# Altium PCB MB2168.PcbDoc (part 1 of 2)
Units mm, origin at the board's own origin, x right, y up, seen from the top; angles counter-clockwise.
Board outline 43 x 47 mm, 2 copper layers (Top Layer, Bottom Layer), stack 0.996 mm thick; 88 components, 71 nets, 358 pads, 587 vias.
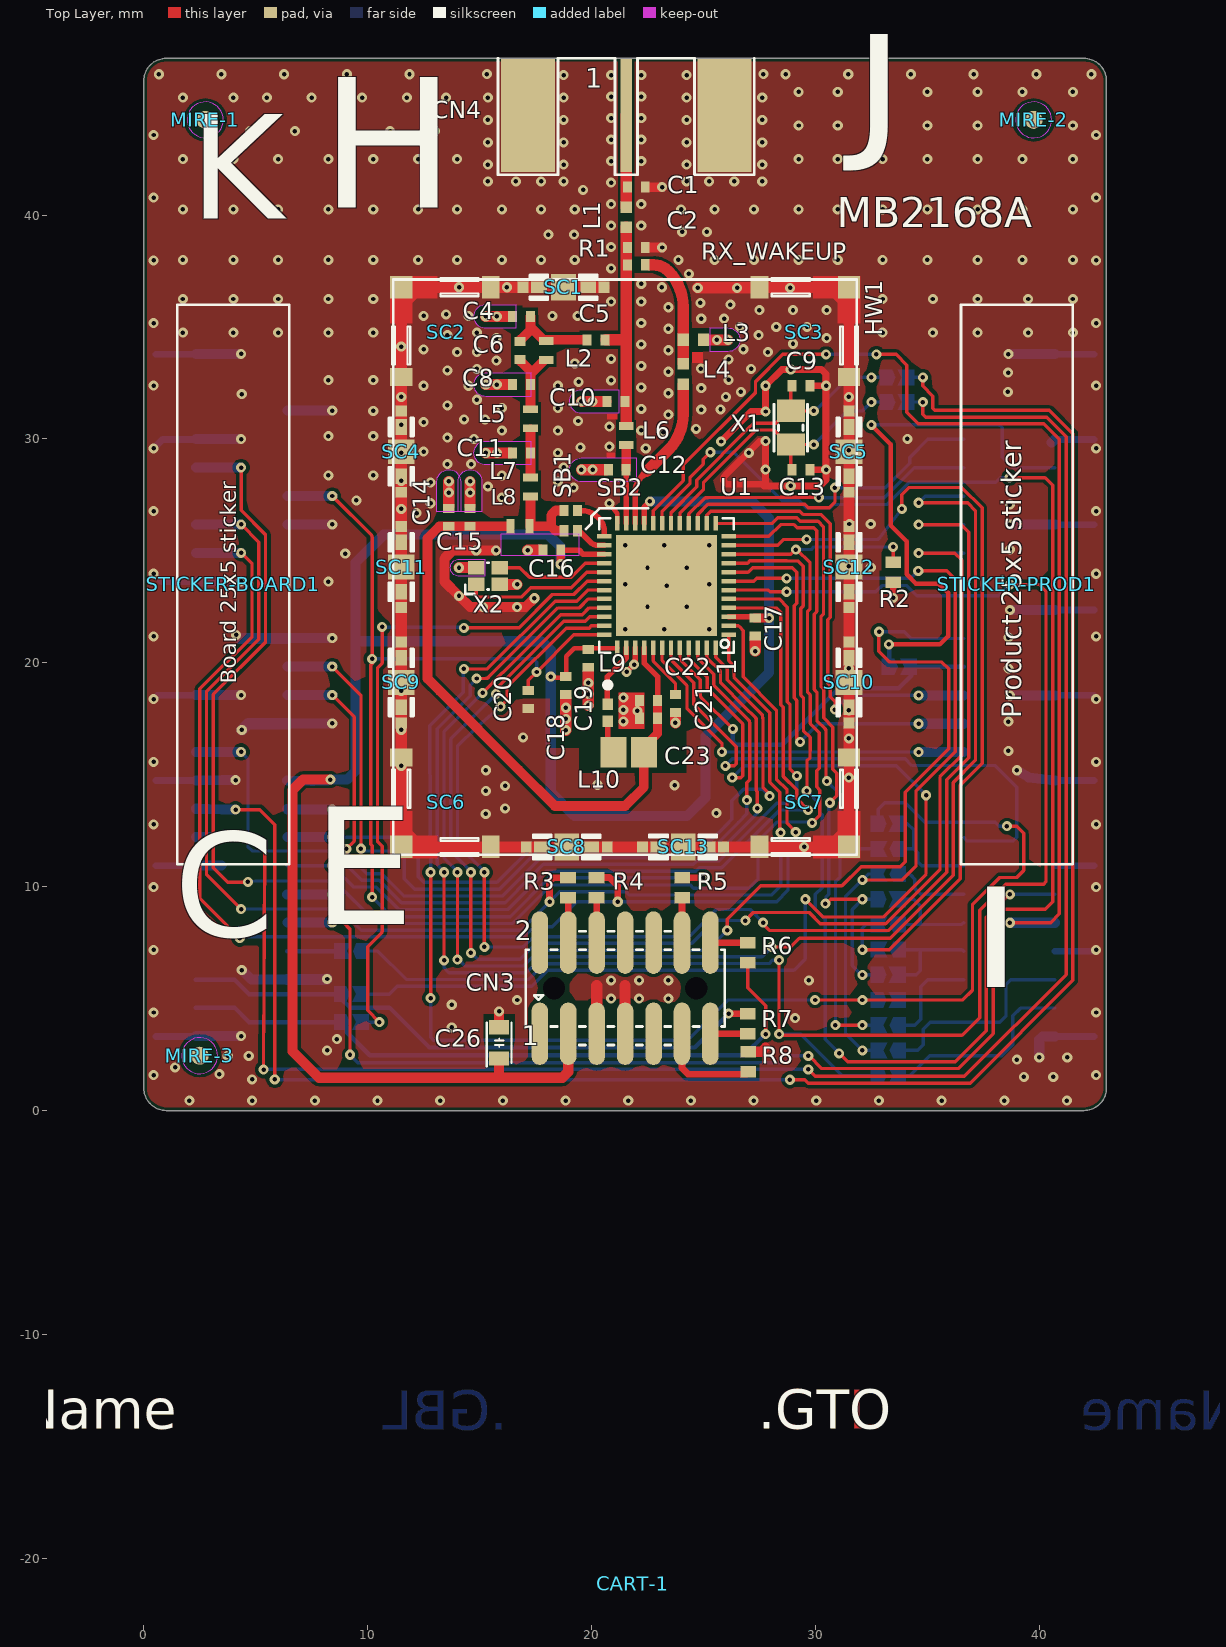
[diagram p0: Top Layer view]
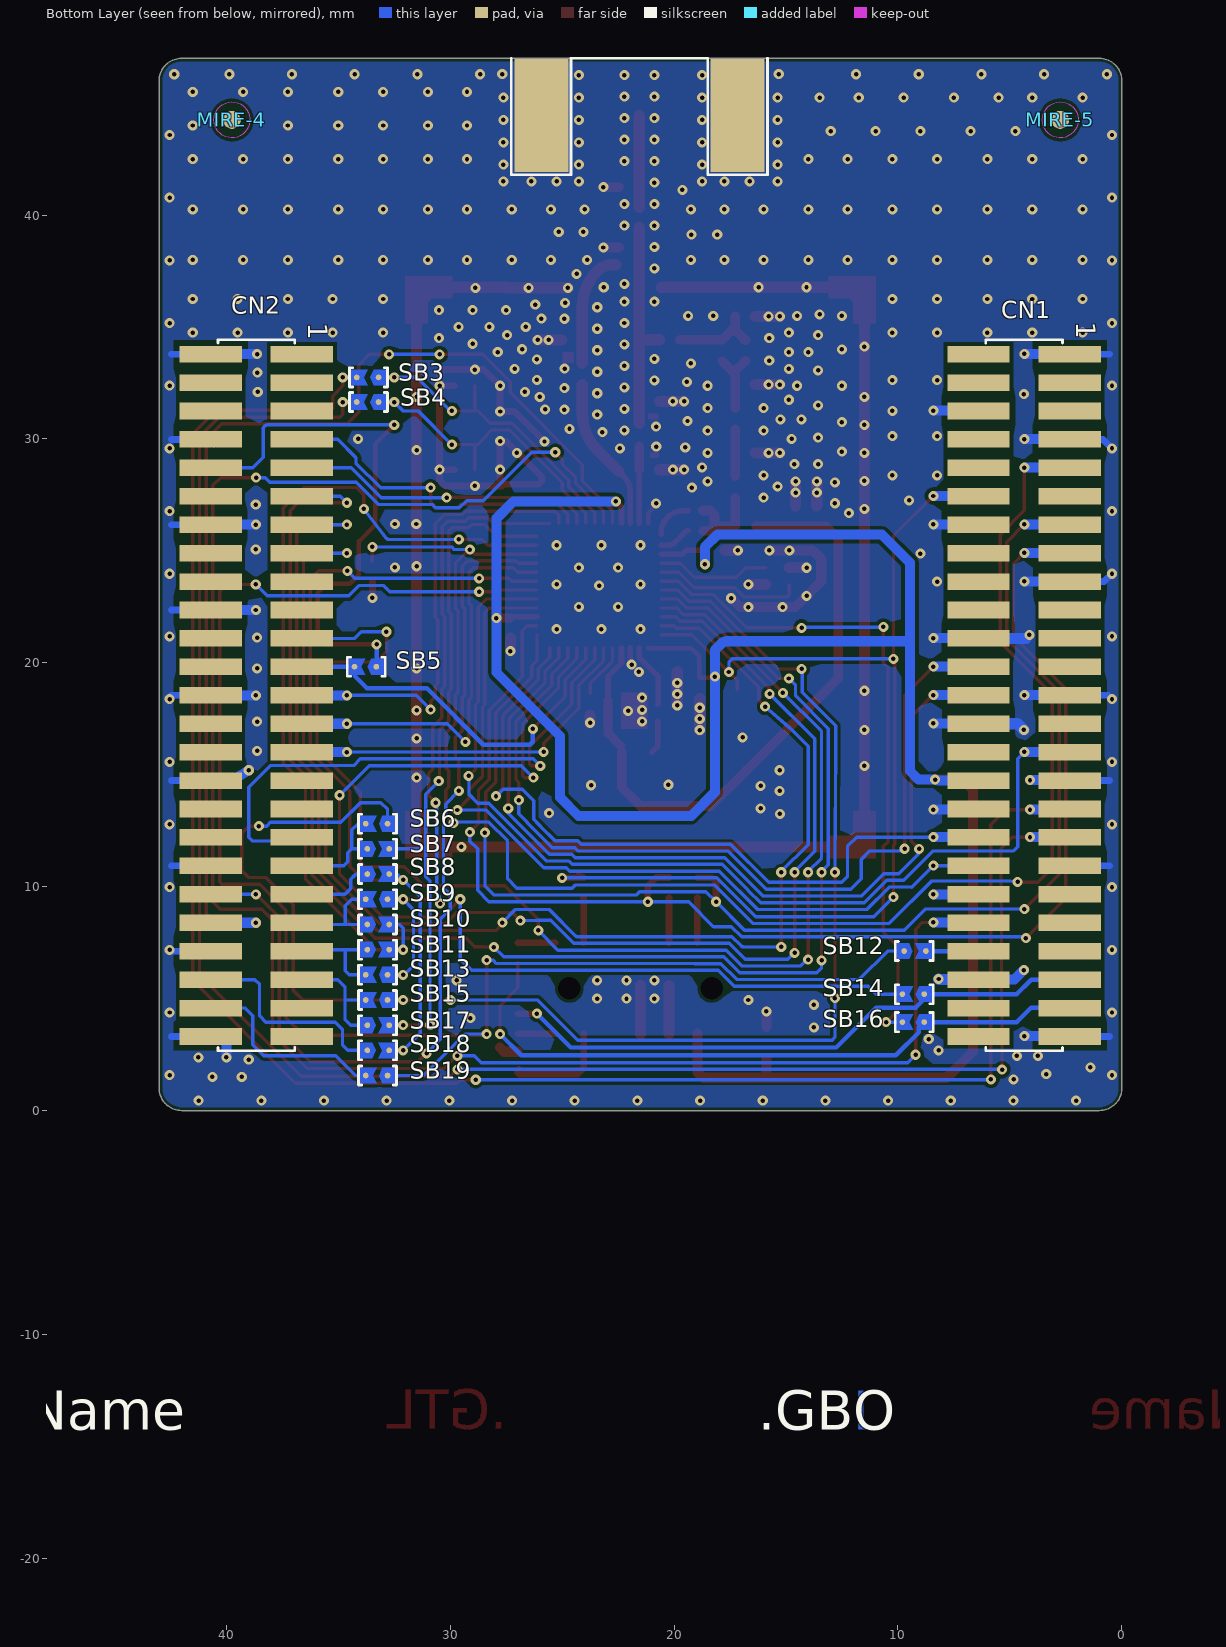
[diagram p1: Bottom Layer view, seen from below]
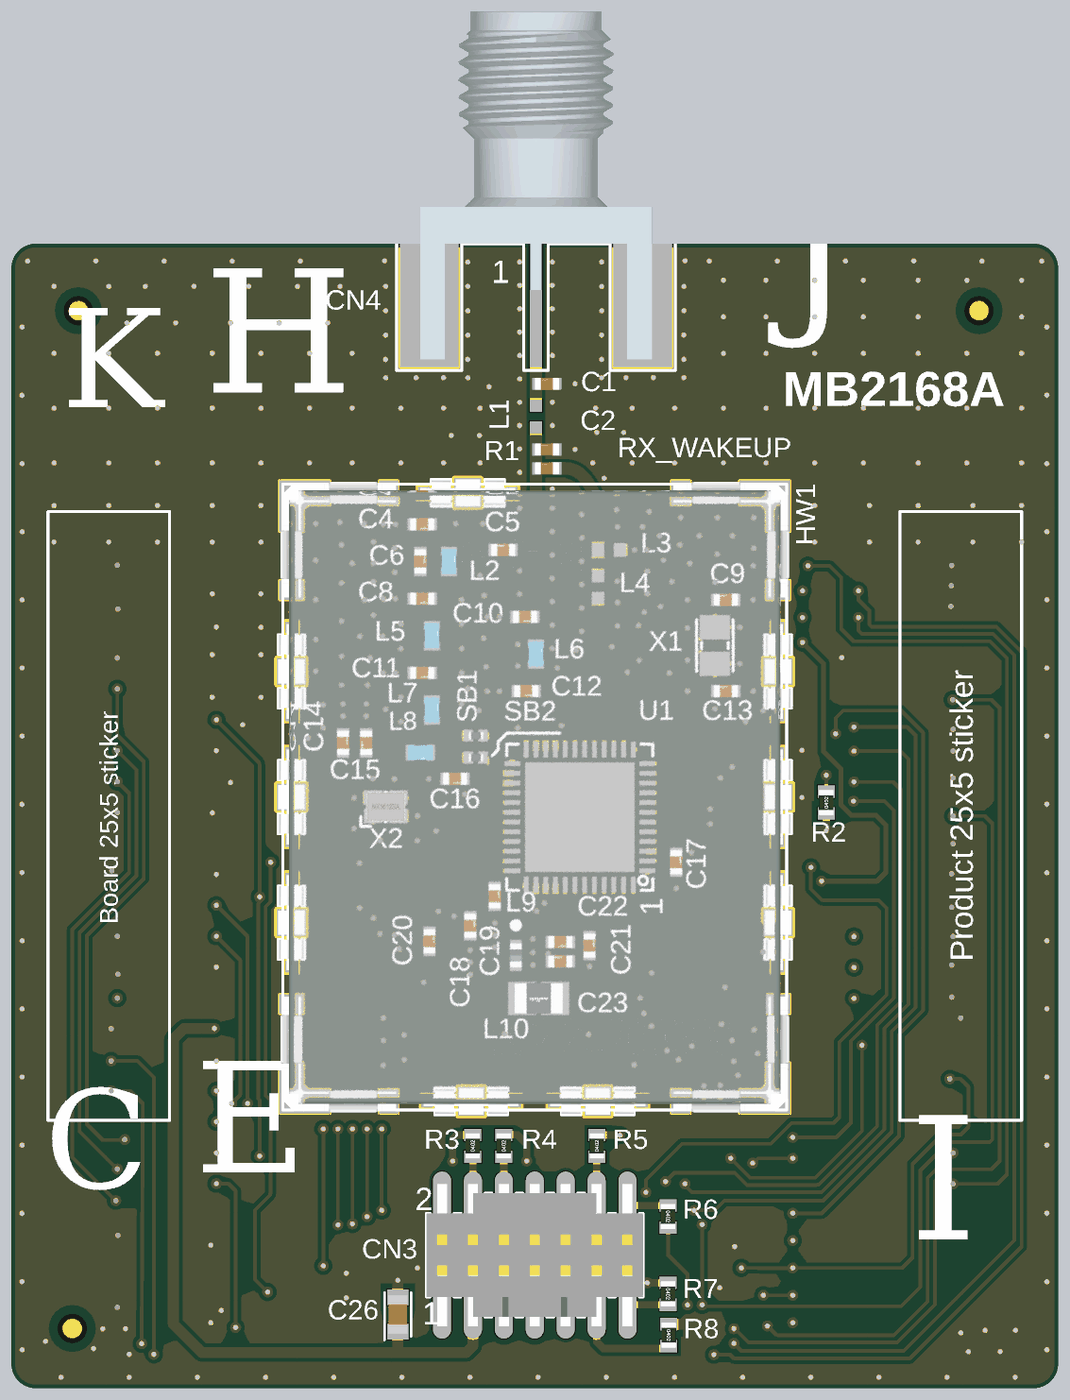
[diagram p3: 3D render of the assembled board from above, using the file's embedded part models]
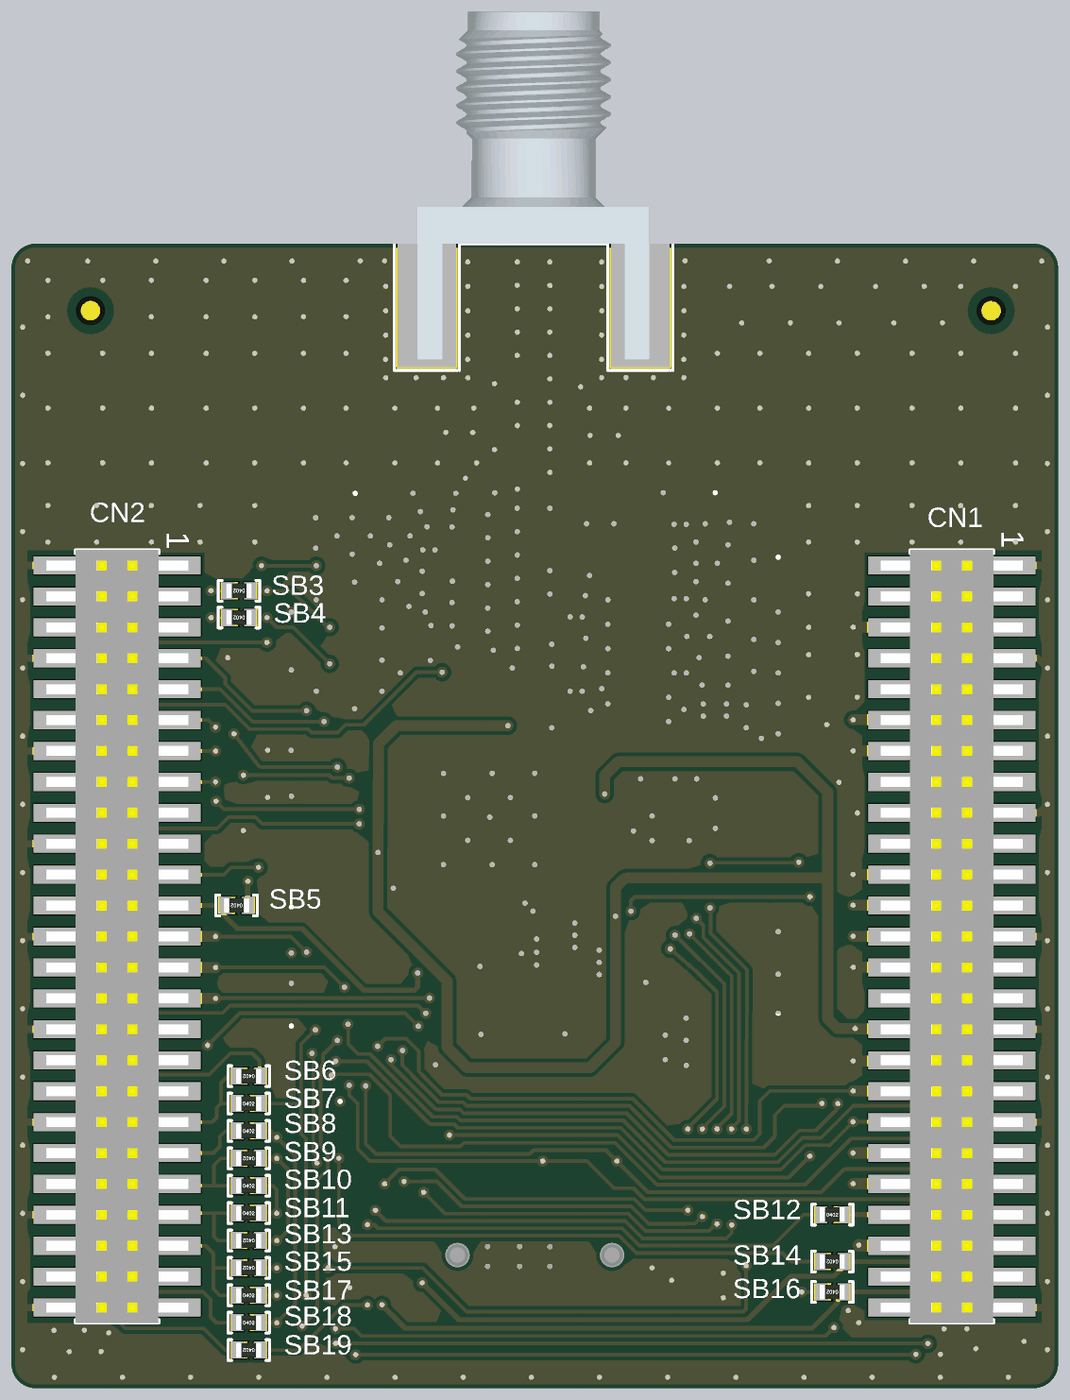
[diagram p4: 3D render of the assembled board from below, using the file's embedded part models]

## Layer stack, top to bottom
Top Solder: solder mask 0.0102, Solder Resist, Dk 3.5
Top Layer: signal copper 0.0406
Dielectric 2: core 0.9144, FR4, Dk 4.3
Bottom Layer: signal copper 0.0406
Bottom Solder: solder mask 0.0102, Solder Resist, Dk 3.5

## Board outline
0,1 ccw(c1,1) 1,0 42,0 ccw(c42,1) 43,1 43,46 ccw(c42,46) 42,47 1,47 ccw(c1,46) 0,46

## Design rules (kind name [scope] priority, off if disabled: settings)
BoardOutlineClearance [All] p1: gap=0.14 ignorepadtopadclearanceinfootprint=FALSE
Clearance Clearance_Keepout [All vs IsKeepOut] p1: gap=0.15 ignorepadtopadclearanceinfootprint=TRUE except(0: Poly-Region)
Clearance Clearance_RF-50R [InNetClass('NC_RF-50R')] p2: gap=0.018 ignorepadtopadclearanceinfootprint=FALSE
Clearance Clearance_Default_Same-net_GND [InNet('GND')] p3: gap=0.15 ignorepadtopadclearanceinfootprint=TRUE except(0: Arc-SMDPad Arc-THPad Arc-Via Track-SMDPad Track-THPad Track-Via SMDPad-Via SMDPad-Hole Via-Via Via-Fill Fill-Region; 0.1: Via-Hole Fill-Hole; 0.12: SMDPad-SMDPad)
Clearance Clearance_Default_Same-net [All] p4: gap=0.15 ignorepadtopadclearanceinfootprint=TRUE except(0.1: Via-Via; 0.12: Arc-SMDPad Track-SMDPad SMDPad-SMDPad)
Clearance Clearance_Default [All] p5: gap=0.15 ignorepadtopadclearanceinfootprint=FALSE except(0.1: Arc-Via Track-Via)
ComponentClearance [All] p1: gap=0.165 collisioncheckmode=3 verticalgap=0.165 showdistances=FALSE
HoleSize [All] p1: absolutevalues=TRUE maxlimit=10 minlimit=0.025 maxpercent=80.000 minpercent=20.000
HoleToHoleClearance [All] p1: gap=0.2 allowstackedmicrovias=TRUE
MinimumSolderMaskSliver [All] p1: minsoldermaskwidth=0.1
PlaneConnect [All] p1: planeconnectstyle=Relief reliefexpansion=0.508 reliefentries=4 reliefconductorwidth=0.21 reliefairgap=0.21
PolygonConnect PolygonConnect_CLIP [TouchesRoom('RoomDefinition')or TouchesRoom('RoomDefinition_1') or   TouchesRoom('RoomDefinition_2') or TouchesRoom('RoomDefinition_4') or TouchesRoom('RoomDefinition_3')  or TouchesRoom('RoomDefinition_5')] p1: connectstyle=Direct reliefconductorwidth=0.3 reliefentries=4 polygonreliefangle="90 Angle" airgapwidth=0.25
PolygonConnect PolygonConnect_Default_1 [All] p2: thpad.connectstyle=Relief thpad.reliefconductorwidth=0.3 thpad.reliefentries=4 thpad.polygonreliefangle="90 Angle" thpad.airgapwidth=0.25 smdpad.connectstyle=NoConnect smdpad.reliefconductorwidth=0.254 smdpad.reliefentries=4 smdpad.polygonreliefangle="90 Angle" smdpad.airgapwidth=0.254 via.connectstyle=Direct via.reliefconductorwidth=0.254 via.reliefentries=4 via.polygonreliefangle="90 Angle" via.airgapwidth=0.254
RoomDefinition RoomDefinition_3 [False vs False] p1: confinementstyle=ConfineIn formatcopy=TRUE lockcomponents=FALSE outline 22.24,41.754 23.159,41.754 23.159,38.308 22.24,38.308
RoomDefinition RoomDefinition_4 [False vs False] p2: confinementstyle=ConfineIn formatcopy=TRUE lockcomponents=FALSE outline 16.668,18.313 18.139,18.313 18.139,17.066 16.668,17.066
RoomDefinition RoomDefinition_2 [False] p3: confinementstyle=ConfineIn formatcopy=TRUE lockcomponents=FALSE outline 27.072,12.919 27.072,10.495 16.087,10.495 16.087,12.919
RoomDefinition RoomDefinition_1 [False] p4: confinementstyle=ConfineIn formatcopy=TRUE lockcomponents=FALSE outline 32.674,15.775 30.25,15.775 30.25,28.309 32.674,28.309
RoomDefinition [False] p5: confinementstyle=ConfineIn formatcopy=TRUE lockcomponents=FALSE outline 12.674,16.465 10.25,16.465 10.25,27.45 12.674,27.45
RoutingVias RoutingVias_Default [All] p1: holewidth=0.3 width=0.6 viastyle="Through Hole" minholewidth=0.3 minwidth=0.6 maxholewidth=0.3 maxwidth=0.6 useviatemplates=TRUE viatemplateguid#1={7280008E-C29C-4D1A-93D7-D7784B042BC4} viatemplatename#1=v45h20m0mx0
SilkToSilkClearance [All] p1 off: silktosilkclearance=0.2
SilkToSolderMaskClearance [IsPad] p1 off: minsilkscreentomaskgap=0.2 clearancetoexposedcopper=TRUE
SolderMaskExpansion [All] p1: expansion=0.102 istentingtop=FALSE
ViasUnderSMD [InPadClass('PC__VIAS-IN-PAD')] p1: allowed=TRUE
Width Width_RF-50R [InNetClass('NC_RF-50R')] p1: maxlimit=0.55 minlimit=0.25 preferedwidth=0.51 impedanceprofiledriven=TRUE impedanceprofileid={AD1550EC-3D0E-4E34-9E21-FD44D1EEEC04} impedanceprofilevalue=50.000000 minimp=50.000000 maximp=50.000000 favimp=50.000000
Width Width_Default [All] p2: maxlimit=10 minlimit=0.15 preferedwidth=0.2
23 further rules are at their usual default settings.

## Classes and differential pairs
pad class PC__VIAS-IN-PAD: C22-1 C22-2 C23-1 C23-2 U1-49
net class NC_RF-50R: NetC1_2 NetC2_2 NetL3_1

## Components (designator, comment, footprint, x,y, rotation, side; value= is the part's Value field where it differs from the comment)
C1 "Capacitor" GRM155--GJM155-0_05-MFG#1 22,41.25 r180 top value=TBD
C2 "Capacitor" GRM155--GJM155-0_05-MFG#1 22,38.55 r180 top value=TBD
C4 "Capacitor" GRM155--GJM155-0_05-MFG#1 16.875,35.475 r0 top value=TBD
C5 "Capacitor" GRM155--GJM155-0_05-MFG#1 20.2,34.425 r180 top value=100pF
C6 "Capacitor" GRM155--GJM155-0_05-MFG#1 16.8,33.95 r90 top value=TBD
C8 "Capacitor" GRM155--GJM155-0_05-MFG#1 16.875,32.425 r0 top value=TBD
C9 "Capacitor" GRM155--GJM155-0_05-MFG#1 29.35,32.375 r180 top value=6.8pF
C10 "Capacitor" GRM155--GJM155-0_05-MFG#1 21.1,31.675 r0 top value=TBD
C11 "Capacitor" GRM155--GJM155-0_05-MFG#1 16.875,29.375 r0 top value=TBD
C12 "Capacitor" GRM155--GJM155-0_05-MFG#1 21.15,28.625 r0 top value=TBD
C13 "Capacitor" GRM155--GJM155-0_05-MFG#1 29.35,28.625 r180 top value=6.8pF
C14 "Capacitor" GRM155--GJM155-0_05-MFG#1 13.625,26.5 r90 top value=100pF
C15 "Capacitor" GRM155--GJM155-0_05-MFG#1 14.575,26.5 r270 top value=100nF
C16 "Capacitor" GRM155--GJM155-0_05-MFG#1 18.225,25.025 r0 top value=100nF
C17 "Capacitor" GRM155--GJM155-0_05-MFG#1 27.31,21.6 r90 top value=100nF
C18 "Capacitor" GRM155--GJM155-0_05-MFG#1 18.852,18.99 r90 top value=4.7uF
C19 "Capacitor" GRM155--GJM155-0_05-MFG#1 19.857,20.2 r90 top value=TBD
C20 "Capacitor" GRM155--GJM155-0_05-MFG#1 17.172,18.352 r90 top value=100nF
C21 "Capacitor" GRM155--GJM155-0_05-MFG#1 23.75,18.175 r90 top value=220nF
C22 "Capacitor" GRM155--GJM155-0_05-MFG#1 22.55,18.321 r0 top value=4.7uF
C23 "Capacitor" GRM155--GJM155-0_05-MFG#1 22.55,17.525 r180 top value=100nF
C26 "Capacitor" C0603 15.875,3.025 r270 top value=1uF
CART-1 "Comment" Sheetbox_4L2S -23.25,-26.5 r0 top
CN1 "FTSH-125-02-L-DV" CON_SAMTEC_FTSH-125-02-L-DV_INV 4.366,18.548 r270 bottom locked value="Header 25x2"
CN2 "FTSH-125-02-L-DV" CON_SAMTEC_FTSH-125-02-L-DV_INV 38.656,18.548 r270 bottom locked value="Header 25x2"
CN3 "Header 7x2" CON_SAMTEC_FTSH-107-01-L-DV-K-A 21.5,5.465 r0 top locked
CN4 "mmcx" CON_SMA-RF_CINCH_142-0701-851 21.55,47 r0 top
HW1 "S02-20150300" SHIELD_HARWIN_S02-25200300_20X25_H3 21.5,24.275 r0 top locked value=S02-25200300R
L1 "Inductor" L0402#1 21.55,39.9 r90 top value=0R
L2 "Inductor" LQW15AN_00-W0_6-0_1-MFG 17.975,33.95 r90 top value=TBD
L3 "Inductor" L0402#2 24.55,34.425 r0 top value=TBD
L4 "Inductor" L0402#1 24.1,32.9 r90 top value=TBD
L5 "Inductor" LQW15AN_00-W0_6-0_1-MFG 17.275,30.9 r90 top value=TBD
L6 "Inductor" LQW15AN_00-W0_6-0_1-MFG 21.55,30.15 r90 top value=TBD
L7 "Inductor" LQW15AN_00-W0_6-0_1-MFG 17.275,27.85 r90 top value=TBD
L8 "Inductor" LQW15AN_00-W0_6-0_1-MFG 16.8,26.1 r0 top value=TBD
L9 "Inductor" LQG15HH_02-IPC_C 20.725,17.773 r270 top value=TBD
L10 "Inductor" LQM21FN_70-IPC_C 21.663,16.008 r180 top value=10µH
MIRE-1 "Comment" MIRE_PLACE_SMD_0P8MM 2.75,44.25 r0 top
MIRE-2 "Comment" MIRE_PLACE_SMD_0P8MM 39.75,44.25 r0 top
MIRE-3 "Comment" MIRE_PLACE_SMD_0P8MM 2.5,2.45 r0 top
MIRE-4 "Comment" MIRE_PLACE_SMD_0P8MM 39.75,44.25 r180 bottom
MIRE-5 "Comment" MIRE_PLACE_SMD_0P8MM 2.75,44.25 r180 bottom
R1 "Resistor" GRM155--GJM155-0_05-MFG#2 22,37.775 r180 top value=0
R2 "Resistor" R0402 33.475,24.05 r90 top value=100K
R3 "Resistor" R0402 18.95,9.95 r90 top value=47R
R4 "Resistor" R0402 20.225,9.95 r90 top value=47R
R5 "Resistor" R0402 24.05,9.95 r90 top value=47R
R6 "Resistor" R0402 26.975,7.05 r270 top value=47R
R7 "Resistor" R0402 26.975,3.875 r270 top value=47R
R8 "Resistor" R0402 27.003,2.175 r270 top value=47R
SB1 "SB_ON" SOLDER-BRIDGE_R0201_0R 19.075,26.8 r180 top value=0R
SB2 "SB_ON" SOLDER-BRIDGE_R0201_0R 19.075,25.9 r180 top value=0R
SB3 "SB_ON" SOLDER-BRIDGE_R0402-0R 33.65,32.747 r0 bottom
SB4 "SB_ON" SOLDER-BRIDGE_R0402-0R 33.65,31.647 r0 bottom
SB5 "SB_ON" SOLDER-BRIDGE_R0402-0R 33.75,19.825 r0 bottom
SB6 "SB_ON" SOLDER-BRIDGE_R0402-0R 33.25,12.812 r0 bottom
SB7 "SB_ON" SOLDER-BRIDGE_R0402-0R 33.25,11.688 r180 bottom
SB8 "SB_ON" SOLDER-BRIDGE_R0402-0R 33.25,10.563 r180 bottom
SB9 "SB_ON" SOLDER-BRIDGE_R0402-0R 33.25,9.437 r0 bottom
SB10 "SB_ON" SOLDER-BRIDGE_R0402-0R 33.25,8.313 r180 bottom
SB11 "SB_ON" SOLDER-BRIDGE_R0402-0R 33.25,7.187 r180 bottom
SB12 "SB_ON" SOLDER-BRIDGE_R0402-0R 9.275,7.125 r180 bottom
SB13 "SB_ON" SOLDER-BRIDGE_R0402-0R 33.25,6.062 r0 bottom
SB14 "SB_ON" SOLDER-BRIDGE_R0402-0R 9.275,5.2 r0 bottom
SB15 "SB_ON" SOLDER-BRIDGE_R0402-0R 33.25,4.938 r0 bottom
SB16 "SB_ON" SOLDER-BRIDGE_R0402-0R 9.275,3.95 r0 bottom
SB17 "SB_ON" SOLDER-BRIDGE_R0402-0R 33.25,3.812 r180 bottom
SB18 "SB_ON" SOLDER-BRIDGE_R0402-0R 33.25,2.688 r180 bottom
SB19 "SB_ON" SOLDER-BRIDGE_R0402-0R 33.25,1.562 r0 bottom
SC1 "Shield-clip_S0951-46R" CLIP_HARWIN_S0951-46R 18.75,36.775 r180 top value=S0951-46R
SC2 "Shield-clip_S0951-46R" CLIP_HARWIN_S0981-46R 11.5,36.775 r180 top value=S0981-46R
SC3 "Shield-clip_S0951-46R" CLIP_HARWIN_S0981-46R 31.5,36.775 r90 top value=S0981-46R
SC4 "Shield-clip_S0951-46R" CLIP_HARWIN_S0951-46R 11.5,29.433 r90 top value=S0951-46R
SC5 "Shield-clip_S0951-46R" CLIP_HARWIN_S0951-46R 31.5,29.433 r90 top value=S0951-46R
SC6 "Shield-clip_S0951-46R" CLIP_HARWIN_S0981-46R 11.5,11.775 r270 top value=S0981-46R
SC7 "Shield-clip_S0951-46R" CLIP_HARWIN_S0981-46R 31.5,11.775 r0 top value=S0981-46R
SC8 "Shield-clip_S0951-46R" CLIP_HARWIN_S0951-46R 18.89,11.774 r180 top value=S0951-46R
SC9 "Shield-clip_S0951-46R" CLIP_HARWIN_S0951-46R 11.5,19.12 r90 top value=S0951-46R
SC10 "Shield-clip_S0951-46R" CLIP_HARWIN_S0951-46R 31.5,19.12 r270 top value=S0951-46R
SC11 "Shield-clip_S0951-46R" CLIP_HARWIN_S0951-46R 11.5,24.278 r90 top value=S0951-46R
SC12 "Shield-clip_S0951-46R" CLIP_HARWIN_S0951-46R 31.5,24.278 r270 top value=S0951-46R
SC13 "Shield-clip_S0951-46R" CLIP_HARWIN_S0951-46R 24.09,11.775 r0 top value=S0951-46R
STICKER-BOARD1 "Comment" STICKER_BOARD_25X5 4,23.5 r90 top
STICKER-PROD1 "Comment" STICKER_PRODUCT_25X5 39,23.5 r90 top
U1 "STM32WL33" ICC_QFN48-EPAD-4P5X4P5_6X6_P040 23.35,23.45 r180 top
X1 "XTAL_2_PINS" CRY_NX2012SA_2P 28.9,30.5 r90 top value=32.768kHz
X2 "XTAL_4_PINS" CRY_NX1612SA_4P 15.38,23.875 r0 top value=48MHz

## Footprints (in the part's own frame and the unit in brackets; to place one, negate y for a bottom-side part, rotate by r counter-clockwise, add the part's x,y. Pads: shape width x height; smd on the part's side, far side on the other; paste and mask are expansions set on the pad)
C0603 [mm]
  rect 0.64x0.89 smd mask+0.05: 1(-0.7,0) 2(0.7,0)
  silkscreen extent -0.9,-0.55 1.05,0.55, body extent -0.9,-0.5 0.9,0.5, height 1.4
CLIP_HARWIN_S0951-46R [mm] "MCD-01587_CLIP-X1"
  rect 0.48x0.5 smd mask+0.1: 1(-1.81,0) 1(1.81,0)
  rect 0.7x0.5 smd mask+0.1: 1(-1.1,0) 1(1.1,0)
  rect 1.1x1.2 smd mask+0.1: 1(0,0)
  silkscreen extent -1.5,-0.55 1.5,0.55, body extent -2.05,-0.65 2.05,0.65, height 1.28
CLIP_HARWIN_S0981-46R [mm] "MCD-02164"
  rect 0.8x1 smd mask+0.05: 1(-4,0)
  rect 1x0.8 smd mask+0.05: 1(0,4)
  rect 1x1 smd mask+0.05: 1(0,0)
  Top Layer region: -1.6,-0.5 0.5,-0.5 0.5,1.6 -0.5,1.6 -0.5,0.7 -0.7,0.5 -1.6,0.5
  silkscreen extent -3.45,-0.4 0.4,3.45, body extent -4.3,-0.46 0.46,4.3, height 1.4
CON_SAMTEC_FTSH-107-01-L-DV-K-A [mm] "MCD-01959"
  oval 0.74x2.79 smd mask+0.05: 1(-3.81,-2.035) 2(-3.81,2.035) 3(-2.54,-2.035) 4(-2.54,2.035) 5(-1.27,-2.035) 6(-1.27,2.035) 7(0,-2.035) 8(0,2.035) 9(1.27,-2.035) 10(1.27,2.035) 11(2.54,-2.035) 12(2.54,2.035) 13(3.81,-2.035) 14(3.81,2.035)
  round 0 hole 1 unplated paste-2539.97 mask+0.05: NPTH1(-3.175,0) NPTH2(3.175,0)
  silkscreen extent -4.44,-2.54 4.44,2.54, body extent -4.44,-2.92 4.45,2.92, height 6.12
CON_SAMTEC_FTSH-125-02-L-DV_INV [mm]
  rect 0.74x2.79 smd mask+0.05: 1(-15.24,2.035) 2(-15.24,-2.035) 3(-13.97,2.035) 4(-13.97,-2.035) 5(-12.7,2.035) 6(-12.7,-2.035) 7(-11.43,2.035) 8(-11.43,-2.035) 9(-10.16,2.035) 10(-10.16,-2.035) 11(-8.89,2.035) 12(-8.89,-2.035) 13(-7.62,2.035) 14(-7.62,-2.035) 15(-6.35,2.035) 16(-6.35,-2.035) 17(-5.08,2.035) 18(-5.08,-2.035) 19(-3.81,2.035) 20(-3.81,-2.035) 21(-2.54,2.035) 22(-2.54,-2.035) 23(-1.27,2.035) 24(-1.27,-2.035) 25(0,2.035) 26(0,-2.035) 27(1.27,2.035) 28(1.27,-2.035) 29(2.54,2.035) 30(2.54,-2.035) 31(3.81,2.035) 32(3.81,-2.035) 33(5.08,2.035) 34(5.08,-2.035) 35(6.35,2.035) 36(6.35,-2.035) 37(7.62,2.035) 38(7.62,-2.035) 39(8.89,2.035) 40(8.89,-2.035) 41(10.16,2.035) 42(10.16,-2.035) 43(11.43,2.035) 44(11.43,-2.035) 45(12.7,2.035) 46(12.7,-2.035) 47(13.97,2.035) 48(13.97,-2.035) 49(15.24,2.035) 50(15.24,-2.035)
  silkscreen extent -15.88,-1.71 15.88,1.71, body extent -15.87,-2.92 15.88,2.92, height 4.82
CON_SMA-RF_CINCH_142-0701-851 [mil] "MCD-02072"
  rect 20.08x200 smd mask+1.97: 1(0,-100)
  rect 95x200 smd mask+1.97: 2(172.48,-100) 3(-172.48,-100)
  rect 95x200 smd far side mask+1.97: 4(-172.48,-100) 5(172.48,-100)
  silkscreen extent -225,-205 225,0, body extent -189,-187 189,376, height 161
CRY_NX1612SA_4P [mm] "MCD-02262"
  rect 0.75x0.6 smd mask+0.038: 1(-0.525,-0.375) 2(0.525,-0.375) 3(0.525,0.375) 4(-0.525,0.375)
  silkscreen extent -1.02,-0.8 0.03,0.6, body extent -0.8,-0.6 0.8,0.6, height 0.31
CRY_NX2012SA_2P [mm]
  rect 1x1.25 smd mask+0.05: 1(-0.75,0) 2(0.75,0)
  silkscreen extent -1.05,-0.75 1.05,0.75, body extent -1.05,-0.63 1.05,0.63, height 0.6
GRM155--GJM155-0_05-MFG#1 [mm]
  rect 0.4x0.5 smd paste+0 mask+0: 1(-0.4,0) 2(0.4,0)
  body extent -0.7,-0.38 0.7,0.38, height 0.25
GRM155--GJM155-0_05-MFG#2 [mm]
  rect 0.4x0.51 smd paste+0 mask+0: 1(-0.4,0)
  rect 0.4x0.5 smd paste+0 mask+0: 2(0.4,0)
  body extent -0.7,-0.38 0.7,0.38, height 0.25
ICC_QFN48-EPAD-4P5X4P5_6X6_P040 [mm] "MCD-03488"
  rect 0.65x0.2 smd mask+0.05: 1(-2.775,2.2) 2(-2.775,1.8) 3(-2.775,1.4) 4(-2.775,1) 5(-2.775,0.6) 6(-2.775,0.2) 7(-2.775,-0.2) 8(-2.775,-0.6) 9(-2.775,-1) 10(-2.775,-1.4) 11(-2.775,-1.8) 12(-2.775,-2.2) 25(2.775,-2.2) 26(2.775,-1.8) 27(2.775,-1.4) 28(2.775,-1) 29(2.775,-0.6) 30(2.775,-0.2) 31(2.775,0.2) 32(2.775,0.6) 33(2.775,1) 34(2.775,1.4) 35(2.775,1.8) 36(2.775,2.2)
  rect 0.2x0.65 smd mask+0.05: 13(-2.2,-2.775) 14(-1.8,-2.775) 15(-1.4,-2.775) 16(-1,-2.775) 17(-0.6,-2.775) 18(-0.2,-2.775) 19(0.2,-2.775) 20(0.6,-2.775) 21(1,-2.775) 22(1.4,-2.775) 23(1.8,-2.775) 24(2.2,-2.775) 37(2.2,2.775) 38(1.8,2.775) 39(1.4,2.775) 40(1,2.775) 41(0.6,2.775) 42(0.2,2.775) 43(-0.2,2.775) 44(-0.6,2.775) 45(-1,2.775) 46(-1.4,2.775) 47(-1.8,2.775) 48(-2.2,2.775)
  rect 4.5x4.5 smd mask+0.05: 49(0,0)
  silkscreen extent -3,-3 3,3, body extent -3,-3 3,3, height 0.91
L0402#1 [mm]
  rect 0.51x0.51 smd mask+0.05: 1(-0.45,0) 2(0.45,0)
  body extent -0.5,-0.3 0.5,0.3, height 0.51
L0402#2 [mm]
  rect 0.51x0.56 smd mask+0.05: 1(-0.45,0) 2(0.45,0)
  body extent -0.5,-0.3 0.5,0.3, height 0.51
LQG15HH_02-IPC_C [mm]
  rect 0.515x0.472 smd paste+0 mask+0: 1(-0.379,0) 2(0.379,0)
  silkscreen extent -1.36,-0.12 -1.11,0.13, body extent -0.74,-0.38 0.74,0.38, height 0.25
LQM21FN_70-IPC_C [mm]
  rect 1.154x1.356 smd paste+0 mask+0: 1(-0.676,0) 2(0.676,0)
  body extent -1.35,-0.82 1.35,0.82, height 0.25
LQW15AN_00-W0_6-0_1-MFG [mm]
  rect 0.35x0.65 smd paste+0 mask+0: 1(-0.425,0) 2(0.425,0)
  body extent -0.7,-0.45 0.7,0.45, height 0.25
MIRE_PLACE_SMD_0P8MM [mm]
  round 0.8 smd paste-10 mask+0.2: 1(0,0)
  Top Layer keep-out circle w0.01: c0,0 r0.804
R0402 [mm]
  rect 0.51x0.7 smd mask+0.05: 1(-0.45,0) 2(0.45,0)
  body extent -0.52,-0.3 0.52,0.3, height 0.4
Sheetbox_4L2S [mil] "Sheetbox 4 layers / 2 silkscreens"
  round 20 on Mech16: 1(813.78,210.69) 1(2736.9,210.69)
SHIELD_HARWIN_S02-25200300_20X25_H3 [mm] "MCD-03503"
  silkscreen extent -10.35,-12.85 10.35,12.85, body extent -10.1,-12.6 10.1,12.6, height 3.2
SOLDER-BRIDGE_R0201_0R [mm] "MCD-03219"
  rect 0.4x0.5 smd mask+0.05: 1(-0.3,0) 2(0.3,0)
  body extent -0.32,-0.17 0.32,0.17, height 0.26
SOLDER-BRIDGE_R0402-0R [mil] "MCD-01619"
  round 10 smd paste-393.7: 1(-17.72,0) 2(20.67,0)
  Top Layer region: -30.51,-13.78 -30.51,13.78 -8.86,13.78 -2.95,0 -8.86,-13.78
  Top Layer region: 1.48,13.78 8.37,0 1.48,-13.78 30.51,-13.78 30.51,13.78
  silkscreen extent -33,-17 33,17, body extent -20,-12 20,12, height 14
STICKER_BOARD_25X5 [mm] "Sticker to mention board reference + serial number"
  silkscreen extent -12.5,-2.5 12.5,2.5
STICKER_PRODUCT_25X5 [mm] "Sticker to mention board CPN code"
  silkscreen extent -12.5,-2.5 12.5,2.5

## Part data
C1 C2: library part MCD-01600, "Capacitor, MLCC, 1pF, 50V, NPO, +/-0.1pF, 0402, T=0.5mm", Manufacturer=YAGEO, Manufacturer_Part_Number=TBD, Package=0402
C4: library part MCD-03448, "Capacitor, MLCC, 2.7pF, 50V, C0G, +/-0.05pF, C0G, 0402, T=0.5mm", Manufacturer=MURATA, Manufacturer_Part_Number=TBD, Package=0402
C5 C14: library part MCD-03446, "Capacitor, MLCC, 100pF, 50V, COG, 1%, 0402, T=0.5mm", Manufacturer=MURATA, Manufacturer_Part_Number=GCM1555C1H101FA16, Package=0402
C6: library part MCD-02065, "Capacitor, Monolithic CC, 1.2pF, 50V, +/-0.05pf, 0402, T=0.5mm", Manufacturer=MURATA, Manufacturer_Part_Number=TBD, Package=0402
C8: library part MCD-01374, "Capacitor, MLCC, 5.6pF, 50V, NPO, +/-0.1pF, 0402, T=0.5mm", Manufacturer=YAGEO, Manufacturer_Part_Number=TBD, Package=0402
C9 C13: library part MCD-03452, "Capacitor, MLCC, 6.8pF, ±0.05pF, C0G, 50V, 0402, T=0.5mm", Manufacturer=MURATA, Manufacturer_Part_Number=GJM1555C1H6R8WB01, Package=0402
C10: library part MCD-02994, "Capacitor, MLCC, 1.5pF, 50V, C0G, +/-0.25pF, 0402, T=0.5mm", Manufacturer=MURATA, Manufacturer_Part_Number=TBD, Package=0402
C11: library part MCD-03555, "Capacitor, MLCC, 5.3pF, 50V, C0G, +/-0.1pF, 0402, T=0.5mm", Manufacturer=MURATA, Manufacturer_Part_Number=TBD, Package=0402
C12: library part MCD-02215, "Capacitor, MLCC, 0.5pF, 50V, C0G, +/-0.1pF, 0402, T=0.5mm", Manufacturer=MURATA, Manufacturer_Part_Number=TBD, Package=0402
C15 C23: library part MCD-03442, "Capacitor, MLCC, 100nF, ±10%, X7R, 25V, 0402, T=0.5mm", Manufacturer=MURATA, Manufacturer_Part_Number=GRM155R71E104KE14D, Package=0402
C16 C17: library part MCD-03442, "Capacitor, MLCC, 100nF, +/-10%, X7R, 25V, 0402, T=0.5mm", Manufacturer=MURATA, Manufacturer_Part_Number=GRM155R71E104KE14D, Package=0402
C18 C22: library part MCD-03431, "Capacitor, MLCC, 4.7uF, X5R, 10 V, 0402, ± 20%, T=0.5mm", Manufacturer=MURATA, Manufacturer_Part_Number=GRM155R61A475MEAAD, Package=0402
C19: library part MCD-03442, "Capacitor, MLCC, 100nF, ±10%, X7R, 25V, 0402, T=0.5mm", Manufacturer=MURATA, Manufacturer_Part_Number=TBD, Package=0402
C20: library part MCD-00006, "Capacitor, MLCC, 100nF, 16V, X7R, +/-10%, 0402, T=0.5mm", Alternate_Manufacturer=MURATA, Alternate_Manufacturer_Part_Number=GCM155R71C104KA55D, Manufacturer=YAGEO, Manufacturer_Part_Number=CC0402KRX7R7BB104, Package=C0402
C21: library part MCD-03077, "Capacitor, MLCC, 220nF, 35V, X6S, +/-10%, 0402, T=0.5mm", Manufacturer=MURATA, Manufacturer_Part_Number=GRM155C8YA224KE01D, Package=0402
C26: library part MCD-00010, "Capacitor, MLCC, 1uF, 16V, X5R, 10%, 0603, T=0,8mm", Manufacturer=YAGEO, Manufacturer_Part_Number=CC0603KRX5R7BB105, Package=C0603
CART-1: library part MCD-00279
CN1 CN2: library part MCD-02746, "Header, 25x2, 12.7mm, VR, SMD, T=4.83mm", Manufacturer=SAMTEC
CN3: library part MCD-01531, "Header, 7x2, 1.27mm, VR, T=5.97mm, FTSH series STDC14 without Alignment Pin", Manufacturer=SAMTEC, Manufacturer_Part_Number=FTSH-107-01-L-DV-K
CN4: library part MCD-02072, "Jack_SMA, VR, PCB edge, 50R, T=7.92mm", Alternate_Manufacturer=N/A, Manufacturer=CINCH, Manufacturer_Part_Number=142-0711-881
HW1: library part MCD-03503, "RFI shield CAN, 25x20x3mm", Manufacturer=HARWIN, Manufacturer_Part_Number=S02-25200300R, Package=25x20x3mm
L1: library part MCD-01937, "Resistor, 0R, 0402, +/-5%, 1/16W", Manufacturer=YAGEO, Manufacturer_Part_Number=RC0402JR-070RL, Package=0402
L2: library part MCD-03460, "Inductor, Wire-wound, 5.6nH, ±0.1nH, 1770mA, 40mR, 0402, T=0.5mm", Manufacturer=MURATA, Manufacturer_Part_Number=TBD, Package=0402
L3: library part MCD-03462, "Inductor, MLCC, 5.6nH, ±0.3nH, 650mA, 180mR, 0402, T=0.5mm", Manufacturer=MURATA, Manufacturer_Part_Number=TBD, Package=0402
L4: library part MCD-03461, "Inductor, 6.8nH, +/-3%, 0.6A, 220mR, 0402, T=0.5mm", Manufacturer_Part_Number=TBD
L5: library part MCD-03459, "Inductor, Wire-wound, 6.2nH, ±0.1nH, 1600mA, 56mR, 0402, T=0.5mm", Manufacturer=MURATA, Manufacturer_Part_Number=TBD, Package=0402
L6: library part MCD-01766, "Inductor, 15nH, +/-2%, Itemp=460mA max, 0R16, 0402, T= 0.6mm, Qmin=30", Manufacturer_Part_Number=TBD
L7: library part MCD-03457, "Inductor, Wire-wound, 3.6nH, ±0.1nH, 1950mA, 30mR, 0402, T=0.5mm", Manufacturer=MURATA, Manufacturer_Part_Number=TBD, Package=0402
L8: library part MCD-03456, "Inductor, Wire-wound, 12nHH, ±2%, 500mA, 1405mR, 0402, T=0.5mm", Manufacturer=MURATA, Manufacturer_Part_Number=TBD, Package=0402
L9: "Inductor, MLCC, 100nH, ±5%, 200mA, 1.25R, 0402, T=0.5mm", Manufacturer=MURATA, Manufacturer_Part_Number=LQG15HSR10J02, Package=0402
L10: library part MCD-03557, "Inductor, 10uH, +/-20%, 100mA, 1R36, 0805, T=0.8mm", Manufacturer=MURATA, Manufacturer_Part_Number=LQM21FN100M80, Package=0805
R1: library part MCD-03301, "0 ohm resistor", Manufacturer=YAGEO, Manufacturer_Part_Number=RT0402FRE07100KL, Package=0402
R2: library part MCD-03301, "Resistor, 100K, 0402, +/-1%, 1/16W", Manufacturer=YAGEO, Manufacturer_Part_Number=RT0402FRE07100KL, Package=0402
R3 R4 R5 R6 R7 R8: library part MCD-00481, "Resistor,47R,0402,1%,1/16W", Manufacturer=YAGEO, Manufacturer_Part_Number=RC0402FR-0747RL, Package=R0402
SB1 SB2: "Resistor, 0R, 0201, Solder Bridge ON , 1/20W,", Manufacturer=YAGEO, Manufacturer_Part_Number=RC0201JR-070RL, Package=SB0201
SB3 SB4 SB5 SB6 SB7 SB8 SB9 SB10 SB11 SB12 SB13 SB14 SB15 SB16 SB17 SB18 SB19: library part MCD-01618, "Solder Bridge 0402 ON", Manufacturer=YAGEO, Manufacturer_Part_Number=RC0402JR-070RL, Package=SB0402
SC1 SC4 SC5 SC8: library part MCD-01587, "shield clip Harwin S0951-46R to fix RF shielded cavity", Manufacturer=HARWIN, Manufacturer_Part_Number=S0951-46R
SC2 SC3 SC6 SC7: library part MCD-02164, "shield clip Harwin S0981-46R to fix RF shielded cavity - SMT RFI Shield Clip, Corner (T+R)", Manufacturer=HARWIN, Manufacturer_Part_Number=S0981-46R
SC9 SC10 SC11 SC12 SC13: library part MCD-01587, "RFI shield clip mini TIN SMD", Manufacturer=HARWIN, Manufacturer_Part_Number=S0951-46R, Package=1.1x3.9mm
U1: library part MCD-03488, "IC, Programmable Sub-1GHz wireless SoC", Manufacturer=STMICROELECTRONICS, Package=QFN48
X1: library part MCD-01445, "Crystal, 32.768kHz, 7pF, +/-20ppm, 80K, 2.05x1.2mm", Manufacturer=NDK, Manufacturer_Part_Number=NX2012SA-32.768KHZ-EXS00A-MU00389, Package=2.05x1.2mm
X2: library part MCD-03559, "Crystal, 48MHz, 8pF, +/-10 ppm, 22R, 1.6x1.2mm", Manufacturer=NDK, Manufacturer_Part_Number="NX1612SA-48.000 MHz-EXS00A-CS12140", Package=1.6*1.2mm

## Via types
v1: diameter 0.45, hole 0.2, Top Layer to Bottom Layer, tented both sides, 587 vias

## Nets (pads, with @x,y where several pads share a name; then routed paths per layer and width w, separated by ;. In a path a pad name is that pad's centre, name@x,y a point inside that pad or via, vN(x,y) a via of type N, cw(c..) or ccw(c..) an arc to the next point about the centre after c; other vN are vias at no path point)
GND: C1.1 C2.1 C4.1 C8.1 C9.1 C10.1 C11.1 C12.1 C13.1 C14.2 C15.1 C16.1 C17.1 C18.1 C19.1 C20.1 C21.1 C22.1 C23.2 C26.1 CN1.1 CN1.6 CN1.7 CN1.14 CN1.17 CN1.22 CN1.25 CN1.28 CN1.31 CN1.34 CN1.37 CN1.40 CN1.46 CN1.49 CN2.2 CN2.8 CN2.14 CN2.20 CN2.26 CN2.32 CN2.38 CN2.44 CN2.50 CN3.5 CN3.7 CN4.2 CN4.3 CN4.4 CN4.5 L3.2 R2.1 R8.1 SC1.1 SC2.1 SC3.1 SC4.1 SC5.1 SC6.1 SC7.1 SC8.1 SC9.1 SC10.1 SC11.1 SC12.1 SC13.1 U1.24 U1.39 U1.49 X2.2 X2.4 | length 215.7
  Top Layer w0.2: v1(20.801,27.121) 21.113,26.722 cw(c20.975,26.615) 21.131,26.694 21.15,26.656 U1.24@21.15,26.225
  Top Layer w0.25: v1(21.571,19.59) v1(21.9,19.919) ; U1.39@21.95,20.675 21.95,20.202 ; v1(21.9,19.919) 21.9,19.973 v1@21.914,19.987 ; v1(21.9,19.919) v1@21.914,19.987 ; v1@21.914,19.987 21.942,20.121 ccw(c21.55,20.202) 21.95,20.202 ; v1@21.914,19.987 21.95,20.023 21.95,20.202
  Top Layer w0.3: v1@16.675,23.5 v1(16.68,23.505) ; v1(25.787,29.884) 27.128,31.225 27.34,31.225 v1(27.775,31.225) v1(27.775,32.375) 28.5,33.1 v1(28.9,33.1) 30.275,33.1 30.475,32.9 v1(30.475,32.375) ; C13.1@29.8,28.625 v1(30.475,28.625) ; C9.1@29.8,32.375 v1(30.475,32.375) ; v1(33.475,22.895) R2.1@33.475,23.6 ; 27.775,27.975 26.118,27.975 cw(c26.118,28.2) 25.959,28.359 27.491,29.891 27.766,29.891 v1(27.775,29.9) v1(27.775,28.625) 27.775,27.975 ; 27.775,27.975 27.7,27.9 v1(28.9,27.9) 30.214,27.9 30.475,28.161 v1(30.475,28.625) ; v1(30.475,28.625) v1(30.475,32.375)
  Top Layer w0.43: C2.1@22.45,38.55 v1(23.155,38.55) ; C1.1@22.45,41.25 v1(23.155,41.25)
  Top Layer w0.45: v1(14.08,24.245) v1@14.085,24.25 ; v1(15.74,25.025) v1(14.85,25.025) 13.809,25.025 13.425,24.642 13.425,23.642 v1(14.08,22.988) 14.58,22.488 v1(15.155,22.488) v1(16.68,22.488) 17.053,22.488 v1(17.449,22.883) ; C26.1@15.875,3.725 v1(15.875,4.43) ; R8.1@27.003,2.625 27.587,2.625 27.775,2.812
  Top Layer w0.5: C14.2@13.625,27 v1(13.625,27.6) v1(13.625,28.1) ; v1@14.085,24.25 X2.4@14.855,24.25 ; C15.1@14.575,27 v1(14.575,27.6) v1(14.575,28.1) ; v1(15.275,29.375) v1(15.775,29.375) C11.1@16.375,29.375 ; v1(15.275,32.425) v1(15.775,32.425) C8.1@16.375,32.425 ; v1(15.275,35.475) v1(15.775,35.475) C4.1@16.375,35.475 ; X2.2@15.905,23.5 v1@16.675,23.5 ; SC1.1@16.94,36.775 v1(16.22,36.775) SC2.1@15.5,36.775 SC2.1@11.5,36.775 v1(11.5,34.125) SC2.1@11.5,32.775 SC4.1@11.5,31.243 SC4.1@11.5,30.533 SC4.1@11.5,29.433 v1(11.5,29.375) SC4.1@11.5,28.333 SC4.1@11.5,27.623 SC11.1@11.5,26.088 SC11.1@11.5,25.378 SC11.1@11.5,24.278 SC11.1@11.5,23.178 SC11.1@11.5,22.468 SC9.1@11.5,20.93 SC9.1@11.5,20.22 SC9.1@11.5,19.12 SC9.1@11.5,18.02 SC9.1@11.5,17.31 SC6.1@11.5,15.775 v1(11.5,15.395) SC6.1@11.5,11.775 SC6.1@15.5,11.775 19.69,11.775 23.31,11.775 SC7.1@27.5,11.775 v1(29.5,11.775) SC7.1@31.5,11.775 v1(31.5,14.875) SC7.1@31.5,15.775 v1(31.5,16.625) v1(31.5,17.875) v1(31.5,19.75) 31.5,22.464 SC5.1@31.5,27.623 SC5.1@31.5,28.333 SC5.1@31.5,29.433 SC5.1@31.5,30.533 SC5.1@31.5,31.243 SC3.1@31.5,32.775 SC3.1@31.5,36.775 SC3.1@27.5,36.775 ; SC1.1@16.94,36.775 SC1.1@17.65,36.775 SC1.1@18.75,36.775 SC1.1@19.85,36.775 SC1.1@20.56,36.775 ; v1(17.15,25.025) C16.1@17.725,25.025 ; v1(18.852,16.99) v1(18.852,17.49) v1(18.852,17.99) C18.1@18.852,18.39 ; v1(19.55,28.625) v1(20.05,28.625) C12.1@20.65,28.625 ; v1(19.55,31.675) v1(20.05,31.675) C10.1@20.65,31.675 ; v1(19.857,18.1) v1(19.857,18.6) v1(19.857,19.1) C19.1@19.857,19.6 ; CN3.5@20.23,3.43 20.23,5.575 ; CN3.7@21.5,3.43 21.5,5.575 ; v1(23.75,17.321) C21.1@23.75,17.664 ; v1(24.743,36.75) v1(26.5,36.75) SC3.1@27.475,36.75 ; L3.2@25,34.425 v1(25.6,34.425) v1(26.1,34.425) ; v1(27.31,20.525) C17.1@27.31,21.1
  Bottom Layer w0.3: v1(0.438,18.378) 0.608,18.548 CN1.25@2.331,18.548 ; v1(0.438,23.977) 0.787,23.628 CN1.17@2.331,23.628 ; v1(0.438,29.577) 0.839,29.978 CN1.7@2.331,29.978 ; 0.55,3.308 CN1.49@2.331,3.308 ; 0.55,10.928 CN1.37@2.331,10.928 ; 0.55,14.738 CN1.31@2.331,14.738 ; 0.55,33.788 CN1.1@2.331,33.788 ; v1(4.125,21.25) 4.287,21.088 ; CN2.50@40.691,3.308 42.45,3.308 ; CN2.44@40.691,7.118 v1@42.45,7.118 ; CN2.38@40.691,10.928 42.45,10.928 ; CN2.32@40.691,14.738 42.45,14.738 ; CN2.26@40.691,18.548 v1@42.45,18.548 ; CN2.20@40.691,22.358 42.45,22.358 ; CN2.14@40.691,26.168 42.45,26.168 ; CN2.8@40.691,29.978 42.45,29.978 ; CN2.2@40.691,33.788 42.45,33.788
  Bottom Layer w0.45: CN1.49@2.343,3.32 v1(4.35,3.32) ; CN1.37@2.343,10.94 CN1.37@3.462,10.943 ; CN1.31@2.343,14.75 3.501,14.762 v1(4.101,14.762) ; CN1.25@2.343,18.56 v1(4.35,18.56) ; CN1.17@2.343,23.64 v1(4.35,23.64) ; CN1.7@2.343,29.99 v1(4.35,29.99) ; CN1.1@2.343,33.8 v1(4.35,33.8) ; CN1.37@3.463,10.943 cw(c3.463,10.643) CN1.37@3.465,10.943 ; v1(4.375,6.275) 4.802,5.848 CN1.46@6.401,5.848 ; CN1.40@6.401,9.658 v1(8.42,9.658) ; CN1.34@6.401,13.468 6.432,13.437 v1(8.42,13.437) ; CN1.28@6.413,17.29 v1(8.42,17.29) ; CN1.22@6.413,21.1 v1(8.42,21.1) ; CN1.14@6.413,26.18 v1(8.42,26.18) ; CN1.6@6.413,31.26 v1(8.42,31.26) ; v1(38.625,33.788) CN2.2@40.691,33.788 ; v1(38.684,18.548) CN2.26@40.691,18.548 ; v1(38.684,22.358) CN2.20@40.691,22.358 ; v1(38.684,26.168) CN2.14@40.691,26.168 ; v1(39,15.2) 39.521,14.883 CN2.32@40.691,14.738 ; v1(40,2.375) 40,3.163 40.145,3.308 CN2.50@40.691,3.308 ; CN2.8@40.546,29.833 CN2.8@40.691,29.978
  Bottom Layer w0.5: 4.287,21.088 CN1.22@6.401,21.088 ; v1(4.375,17) 4.653,17.278 CN1.28@6.401,17.278 ; CN1.46@6.401,5.848 8.16,5.848 v1(8.187,5.875)
  other v1: 2.04,0.447 4.84,0.447 7.64,0.447 10.44,0.447 13.24,0.447 16.04,0.447 18.839,0.447 21.639,0.447 24.439,0.447 27.239,0.447 30.039,0.447 32.839,0.447 35.638,0.447 38.438,0.447 41.238,0.447 4.836,1.39 39.312,1.5 40.625,1.5 0.438,1.579 42.538,1.579 3.375,1.625 1.4,1.924 39,2.275 41.25,2.375 3.75,2.438 4.687,2.438 8.187,2.688 8.625,3.187 13.757,3.712 29.098,4.125 0.438,4.378 42.538,4.378 13.757,4.724 16.678,4.938 20.875,5 22.125,5 23.437,5 20.875,5.813 22.125,5.813 23.437,5.813 29.713,5.813 0.438,7.178 42.538,7.178 0.438,9.978 42.538,9.978 0.438,12.778 42.538,12.778 15.275,13.254 25.578,13.281 16.138,13.493 15.282,14.279 16.138,14.501 23.708,14.529 20.258,14.55 15.282,15.2 0.438,15.578 42.538,15.578 38.625,16.063 16.94,16.664 11.5,17 21.425,17.378 38.625,17.375 22.05,17.848 21.425,17.9 42.538,18.378 21.425,18.446 11.5,18.75 38.625,19.75 38.625,21.125 0.438,21.177 42.538,21.177 21.5,21.5 23.25,21.5 25.25,21.5 22.5,22.5 24.25,22.5 23.35,23.45 21.5,23.5 25.25,23.5 8.25,23.625 42.538,23.977 22.5,24.25 24.25,24.25 32.473,24.263 31.497,24.311 9,24.875 38.687,25.063 21.5,25.25 23.25,25.25 25.25,25.25 31.516,26.2 32.473,26.2 12.187,26.688 0.438,26.777 42.538,26.777 11.5,26.875 38.687,27.063 12.812,27.125 9.5,27.25 16,27.375 19.2,27.825 15.375,27.875 12.812,28.062 18.5,28.104 11.5,28.125 8.25,28.375 10.25,28.375 16,28.375 18.75,28.729 13.563,28.875 14.625,28.875 18.5,29.375 27.025,29.375 12.5,29.438 31.5,29.5 22.423,29.576 42.538,29.577 19.5,29.625 20.797,29.654 14.75,30 34.114,30 13.563,30.063 8.25,30.125 10.25,30.125 23.2,30.304 16,30.375 18.5,30.375 22.221,30.38 24.671,30.446 20.801,30.55 11.5,30.625 12.5,30.75 19.4,30.8 14.313,30.875 15.25,30.875 23.43,31.082 10.25,31.25 24.9,31.306 22.221,31.34 25.761,31.321 16,31.375 18.5,31.375 13.563,31.5 14.875,31.75 11.5,31.875 26,31.875 31.5,31.875 4.375,32 23.43,32.041 26.667,32.105 38.597,32.105 24.9,32.265 22.221,32.299 0.438,32.377 12.5,32.375 14.5,32.375 18.5,32.375 42.538,32.377 19.425,32.55 8.25,32.625 10.25,32.625 20.879,32.615 26.125,32.635 38.613,32.959 23.43,33.001 13.563,33.062 14.875,33.125 24.885,33.142 27.125,33.125 22.221,33.259 19.25,33.375 15.75,33.5 26.125,33.55 20.879,33.575 14,33.875 14.875,33.875 27.875,33.875 23.43,33.961 12.5,34 26.788,34.004 22.221,34.219 29,34.25 15.75,34.5 30.5,34.5 13.563,34.635 27.461,34.635 1.75,34.75 4,34.75 6,34.75 8.25,34.75 10.25,34.75 14.875,34.75 33,34.75 35.25,34.75 37.25,34.75 39.5,34.75 41.5,34.75 23.43,34.92 26.625,35 28.25,35 29.625,35 0.438,35.177 22.221,35.178 42.538,35.177 24.9,35.369 25.925,35.375 12.5,35.5 14.5,35.5 18.25,35.5 19.375,35.5 13.5,35.562 27.5,35.75 29,35.75 30.5,35.75 23.43,35.88 26.2,36 24.863,36.075 20.879,36.138 22.221,36.138 1.75,36.25 4,36.25 6,36.25 8.25,36.25 10.25,36.25 33,36.25 35.25,36.25 37.25,36.25 39.5,36.25 41.5,36.25 28.875,36.75 14.085,36.775 23.142,36.775 22.221,36.928 24.35,37.371 20.879,37.613 0.438,37.976 42.538,37.976 1.75,38 4,38 6,38 8.25,38 10.25,38 12.25,38 14,38 16,38 17.75,38 19.25,38 23.883,38 25.5,38 27.25,38 29.25,38 31,38 33,38 35,38 37.25,38 39.25,38 41.5,38 20.879,38.573 18.073,39.125 19.224,39.125 24.05,39.25 25.15,39.25 20.879,39.533 22.221,39.533 1.75,40.25 4,40.25 6,40.25 8.25,40.25 10.25,40.25 12.25,40.25 14,40.25 16,40.25 17.75,40.25 19.25,40.25 24,40.25 25.5,40.25 27.25,40.25 29.25,40.25 31,40.25 33,40.25 35,40.25 37.25,40.25 39.25,40.25 41.5,40.25 20.879,40.492 22.221,40.492 0.438,40.776 42.538,40.776 19.625,41.125 20.879,41.452 15.375,41.5 16.625,41.5 17.75,41.5 18.75,41.5 24.25,41.5 25.25,41.5 26.375,41.5 27.625,41.5 15.375,42.25 18.75,42.25 24.25,42.25 27.625,42.25 20.879,42.411 22.221,42.411 1.75,42.5 4,42.5 6,42.5 8.25,42.5 10.25,42.5 12.25,42.5 14,42.5 29.25,42.5 31,42.5 33,42.5 35,42.5 37.25,42.5 39.25,42.5 41.5,42.5 15.375,43.25 18.75,43.25 24.25,43.25 27.625,43.25 20.879,43.371 22.221,43.371 0.438,43.576 42.538,43.576 4.75,43.75 6.75,43.75 9,43.75 11,43.75 13,43.75 29.25,44 31,44 33,44 35,44 37.25,44 41.5,44 15.375,44.25 18.75,44.25 24.25,44.25 27.625,44.25 20.879,44.331 22.221,44.331 1.75,45.25 4,45.25 5.5,45.25 7.5,45.25 9.75,45.25 11.75,45.25 13.5,45.25 15.375,45.25 18.75,45.25 24.25,45.25 27.625,45.25 20.879,45.29 22.221,45.29 29.25,45.5 31,45.5 33,45.5 35,45.5 37.25,45.5 39.25,45.5 41.5,45.5 18.75,46.25 20.879,46.25 22.221,46.25 24.25,46.25 0.67,46.288 3.47,46.288 6.27,46.288 9.069,46.288 11.869,46.288 15.325,46.3 27.675,46.3 28.668,46.288 31.468,46.288 34.268,46.288 37.068,46.288 39.868,46.288 42.328,46.288
GPIO3/BOOT0: CN1.9 R2.2 U1.10 | length 73.3
  Top Layer w0.15: v1(4.35,28.72) 4.35,26.816 5.436,25.73 5.436,20.922 3.1,18.586 3.1,10.846 3.755,10.191 4.634,10.191 v1(4.653,10.21) ; U1.10@26.125,24.85 28.909,24.85 29.117,25.058 v1(29.124,25.058) 29.172,25.058 29.76,24.47 29.76,22.412 29.649,22.301 29.649,18.682 29.768,18.564 29.768,18.307 29.77,18.305 29.77,17.286 30.175,16.882 30.175,15.295 30.06,15.18 30.06,14.452 30.2,14.313 30.2,13.199 v1(29.85,12.849) ; R2.2@33.475,24.5 v1(33.475,25.175)
  Bottom Layer w0.15: v1(4.653,10.21) 4.978,10.251 cw(c5.006,10.028) 5.006,10.253 8.5,10.253 10.398,8.355 16.486,8.355 18.207,10.076 24.403,10.076 24.553,9.926 27.021,9.926 27.439,10.344 27.439,12.042 28.284,12.887 29.813,12.887 v1(29.85,12.849) ; v1(29.124,25.058) 29.821,25.058 29.937,25.175 v1(33.475,25.175)
  Bottom Layer w0.45: CN1.9@2.343,28.72 v1(4.35,28.72)
GPIO5/SWDIO: CN1.13 R3.2 U1.1 | length 60.5
  Top Layer w0.15: v1(4.35,9) 2.8,10.55 2.8,18.71 5.136,21.046 5.136,25.394 v1(4.35,26.18) ; U1.1@26.125,21.25 26.125,20.099 26.363,19.861 26.363,19.363 27.96,17.765 27.96,14.672 28.412,14.221 28.412,12.447 v1(28.446,12.413)
  Top Layer w0.3: v1(18.125,9.326) 18.125,10.225 18.3,10.4 R3.2@18.95,10.4
  Bottom Layer w0.15: v1(4.35,9) 8.775,9 9.72,8.055 16.854,8.055 v1(18.125,9.326) 18.575,9.776 21.544,9.776 21.694,9.626 28.038,9.626 28.446,10.035 v1(28.446,12.413)
  Bottom Layer w0.45: CN1.13@2.343,26.18 v1(4.35,26.18)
